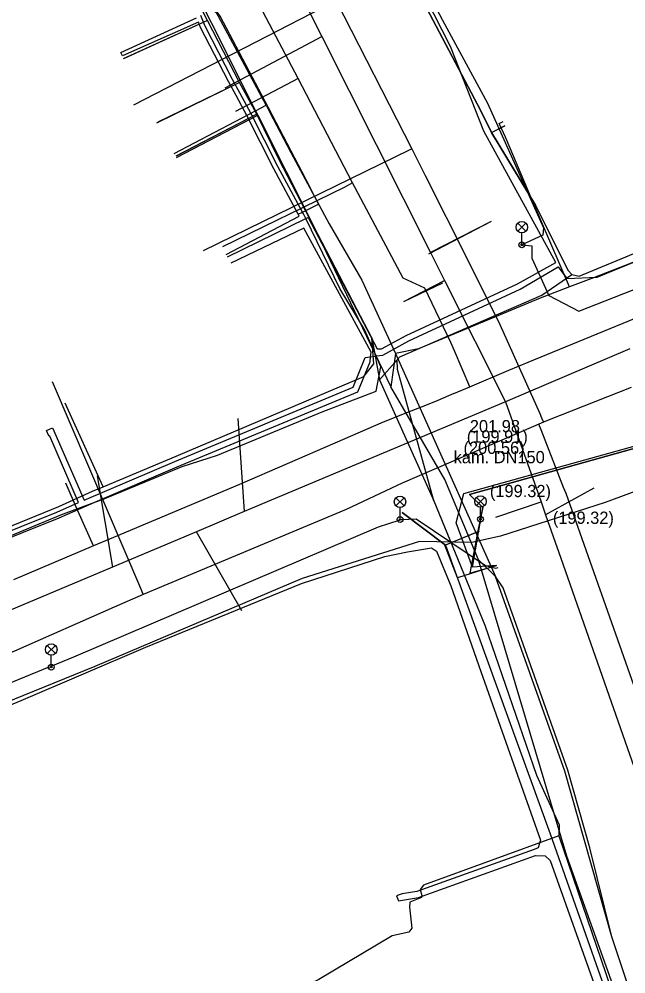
# Model space of a CAD drawing. Extents: x -596228 to -595156, y -1161235 to -1159373.
# Drawn here: x -595920.9 to -595881.3, y -1160772.6 to -1160710.3 of the extents above; entities that cross this region are included whole.
import ezdxf

# ---------------------------------------------------------------- set-up
doc = ezdxf.new("R2010")
doc.units = 0
for name, color, linetype in [('Vrstva 1', 7, 'Continuous'), ('Vrstva 12', 7, 'Continuous'), ('Vrstva 14', 7, 'Continuous'), ('Vrstva 19', 7, 'Continuous'), ('Vrstva 33', 7, 'Continuous'), ('Vrstva 42', 7, 'Continuous'), ('Vrstva 55', 7, 'Continuous'), ('Vrstva 58', 7, 'Continuous'), ('Vrstva 9', 7, 'Continuous')]:
    doc.layers.add(name, color=color, linetype=linetype)

msp = doc.modelspace()

# ---------------------------------------------------------------- linework, layer by layer
at = {"layer": 'Vrstva 1'}
for p, q in [((-595890.14, -1160723.5), (-595894.225, -1160725.63)), ((-595890.14, -1160723.5), (-595894.096, -1160725.519)), ((-595895.84, -1160728.73), (-595893.175, -1160727.35)), ((-595895.84, -1160728.73), (-595893.291, -1160727.511)), ((-595883.44, -1160740.9), (-595886.577, -1160742.651)), ((-595883.44, -1160740.9), (-595886.577, -1160742.651)), ((-595889.83, -1160742.8), (-595886.879, -1160741.799)), ((-595889.83, -1160742.8), (-595886.878, -1160741.799))]:
    msp.add_line(p, q, dxfattribs=at)
at = {"layer": 'Vrstva 12'}
for p, q in [((-595908.65, -1160710.37), (-595914.09, -1160712.85)), ((-595906.56, -1160714.41), (-595908.65, -1160710.37)), ((-595906.56, -1160714.41), (-595911.88, -1160717.02)), ((-595905.42, -1160716.48), (-595906.56, -1160714.41)), ((-595904.82, -1160715.91), (-595905.1, -1160715.38)), ((-595910.81, -1160719.06), (-595905.51, -1160716.27)), ((-595905.42, -1160716.48), (-595910.71, -1160719.23)), ((-595905.51, -1160716.27), (-595904.82, -1160715.91)), ((-595905.51, -1160716.27), (-595905.37, -1160716.55)), ((-595910.66, -1160719.32), (-595905.37, -1160716.55)), ((-595890.12, -1160717.68), (-595889.24, -1160717.24)), ((-595890.06, -1160717.78), (-595890.12, -1160717.68)), ((-595889.31, -1160719), (-595890.06, -1160717.78)), ((-595887.23, -1160722.44), (-595889.31, -1160719)), ((-595880.5, -1160726.03), (-595883.46, -1160727.17)), ((-595883.46, -1160727.17), (-595885.02, -1160727.77)), ((-595897.91, -1160731.09), (-595898.53, -1160729.93)), ((-595897.91, -1160731.09), (-595897.68, -1160732.4)), ((-595897.68, -1160732.4), (-595897.43, -1160733.84)), ((-595896.37, -1160732.11), (-595896.69, -1160734.3)), ((-595896.37, -1160732.11), (-595889.84, -1160746.67)), ((-595915.46, -1160740.82), (-595917.94, -1160735.35)), ((-595890.97, -1160745.58), (-595889.84, -1160746.67)), ((-595877.12, -1160785.47), (-595882.26, -1160770.2))]:
    msp.add_line(p, q, dxfattribs=at)
for points in [[(-595920.87, -1160686.25), (-595919.36, -1160689.21), (-595911.28, -1160704.76), (-595905.51, -1160716.27)], [(-595890.12, -1160717.68), (-595890.8, -1160716.28), (-595892.68, -1160712.73), (-595895.37, -1160707.59), (-595897.16, -1160704.21), (-595899.45, -1160699.85)], [(-595905.1, -1160715.38), (-595908.88, -1160708.31), (-595910.3, -1160705.67), (-595912.55, -1160701.31)], [(-595908.65, -1160710.37), (-595909.66, -1160708.38), (-595911.55, -1160704.72), (-595911.94, -1160704.01)], [(-595898.53, -1160729.93), (-595898.91, -1160729.22), (-595903.96, -1160719.46), (-595905.42, -1160716.48)], [(-595904.82, -1160715.91), (-595904.6, -1160716.33), (-595903.21, -1160718.99), (-595900.71, -1160723.64), (-595898.57, -1160727.32), (-595896.37, -1160732.11)], [(-595905.37, -1160716.55), (-595901.69, -1160723.87), (-595896.69, -1160734.3)], [(-595885.02, -1160727.77), (-595887.45, -1160722.1), (-595889.19, -1160718), (-595889.61, -1160717.09), (-595889.36, -1160716.97)], [(-595884.86, -1160726.96), (-595885.1, -1160726.69), (-595887.23, -1160722.44)], [(-595884.86, -1160726.96), (-595884.4, -1160727.07), (-595881.23, -1160725.75)], [(-595897.43, -1160733.84), (-595896.26, -1160732.53), (-595896.1, -1160732.34), (-595886.83, -1160728.31), (-595884.86, -1160726.96)], [(-595885.02, -1160727.77), (-595886.93, -1160728.51), (-595894.87, -1160731.8), (-595896.37, -1160732.11)], [(-595915.46, -1160740.82), (-595910.68, -1160738.82), (-595898.45, -1160733.62), (-595897.79, -1160732.79), (-595897.91, -1160731.09)], [(-595897.43, -1160733.84), (-595893.88, -1160741.74), (-595890.54, -1160749.86), (-595887.17, -1160759.65), (-595885.69, -1160762.88), (-595885.71, -1160763.61)], [(-595890.97, -1160745.58), (-595893.16, -1160740.35), (-595896.69, -1160734.3)], [(-595926.38, -1160745.37), (-595923.37, -1160744.15), (-595918.35, -1160742.11), (-595916.16, -1160741.11), (-595915.46, -1160740.82)], [(-595877.8, -1160785.64), (-595885.2, -1160764.94), (-595890.97, -1160745.58)], [(-595882.26, -1160770.2), (-595883.69, -1160764.4), (-595885.14, -1160759.33), (-595889.36, -1160747.42), (-595889.84, -1160746.67)], [(-595882.26, -1160770.2), (-595885.33, -1160759.39), (-595889.84, -1160746.67)], [(-595885.71, -1160763.61), (-595894.54, -1160766.83), (-595894.76, -1160767.11), (-595894.66, -1160767.51), (-595894.68, -1160767.63), (-595895.43, -1160767.93), (-595895.47, -1160768.26), (-595895.31, -1160769.63), (-595895.51, -1160769.89), (-595896.59, -1160770.14), (-595901.37, -1160772.99), (-595906.61, -1160775.68), (-595911.39, -1160776.34), (-595914.12, -1160776.08), (-595915.86, -1160775.08), (-595916.37, -1160774.12)], [(-595885.71, -1160763.61), (-595881.71, -1160775.34), (-595877.36, -1160787.44)]]:
    msp.add_lwpolyline(points, dxfattribs=at)
at = {"layer": 'Vrstva 14'}
for p, q in [((-595881.004, -1160734.33), (-595886.451, -1160736.489)), ((-595886.963, -1160736.031), (-595886.851, -1160736.305)), ((-595886.851, -1160736.305), (-595886.721, -1160736.607)), ((-595887.37, -1160736.884), (-595895.93, -1160740.59)), ((-595887.012, -1160736.732), (-595887.37, -1160736.884)), ((-595886.721, -1160736.607), (-595887.012, -1160736.732)), ((-595886.87, -1160737.09), (-595887.012, -1160736.732)), ((-595886.451, -1160736.489), (-595886.721, -1160736.607))]:
    msp.add_line(p, q, dxfattribs=at)
for points in [[(-595926.572, -1160658.791), (-595922.331, -1160666.975), (-595922.126, -1160667.364), (-595921.558, -1160668.432), (-595918.38, -1160674.459), (-595917.977, -1160675.231), (-595917.527, -1160676.095), (-595915.091, -1160680.758), (-595912.991, -1160684.79), (-595910.854, -1160688.921), (-595910.362, -1160689.864), (-595909.965, -1160690.625), (-595908.347, -1160693.726), (-595907.059, -1160696.132), (-595906.224, -1160697.692), (-595904.062, -1160701.813), (-595903.372, -1160703.143), (-595900.25, -1160709.091), (-595895.314, -1160718.754), (-595894.439, -1160720.494), (-595891.712, -1160725.893), (-595889.572, -1160730.225), (-595886.963, -1160736.031)], [(-595900.25, -1160709.091), (-595900.414, -1160709.18), (-595913.485, -1160715.898)], [(-595895.314, -1160718.754), (-595895.476, -1160718.834), (-595908.926, -1160725.411)], [(-595912.84, -1160747.84), (-595912.94, -1160747.61), (-595918.761, -1160733.954)], [(-595867.479, -1160791.46), (-595868.128, -1160789.63), (-595871.59, -1160779.9), (-595885.24, -1160741.26), (-595885.404, -1160740.857), (-595886.87, -1160737.09)], [(-595895.93, -1160740.59), (-595899.6, -1160742.31), (-595912.84, -1160747.84), (-595914.74, -1160748.68), (-595921.25, -1160751.56), (-595923.91, -1160752.66), (-595927.19, -1160754.01), (-595932.66, -1160756.26), (-595933.82, -1160756.75), (-595937.68, -1160758.4), (-595942.37, -1160760.37), (-595945.06, -1160761.51), (-595946.46, -1160762.1), (-595947.85, -1160762.68), (-595962.12, -1160768.63), (-595963.29, -1160769.12), (-595970.02, -1160772), (-595976.93, -1160774.96), (-595977.43, -1160775.17), (-595987.69, -1160779.56), (-595997.69, -1160783.61)]]:
    msp.add_lwpolyline(points, dxfattribs=at)
at = {"layer": 'Vrstva 19'}
for p, q in [((-595902.73, -1160714.155), (-595906.817, -1160716.311)), ((-595899.724, -1160721.268), (-595907.67, -1160725.14)), ((-595899.183, -1160720.963), (-595899.724, -1160721.268)), ((-595891.52, -1160734.29), (-595892.52, -1160731.93))]:
    msp.add_line(p, q, dxfattribs=at)
for points in [[(-595892.52, -1160731.93), (-595892.76, -1160731.39), (-595894.452, -1160727.858), (-595895.878, -1160727.201), (-595899.183, -1160720.963), (-595902.73, -1160714.155), (-595906.047, -1160707.823), (-595906.981, -1160706.086), (-595909.275, -1160701.719), (-595909.609, -1160700.941), (-595911.016, -1160698.292), (-595913.475, -1160693.663), (-595913.599, -1160693.324), (-595913.952, -1160692.775), (-595915.467, -1160689.84), (-595917.901, -1160685.194), (-595920.56, -1160680.118), (-595920.628, -1160679.824), (-595922.636, -1160675.96), (-595924.387, -1160672.545), (-595925.964, -1160669.55), (-595928.051, -1160665.682), (-595931.02, -1160659.823)], [(-595892.57, -1160734.72), (-595891.52, -1160734.29), (-595888.97, -1160733.21), (-595887.72, -1160732.68), (-595879.93, -1160729.49), (-595877.77, -1160728.55), (-595877.08, -1160728.26), (-595875.68, -1160727.65), (-595875.53, -1160727.58)], [(-595892.57, -1160734.72), (-595893.61, -1160735.18), (-595894.41, -1160735.51), (-595895.48, -1160735.93), (-595897.19, -1160736.6), (-595900.34, -1160737.98), (-595906.56, -1160740.67), (-595914.77, -1160744.12), (-595916.09, -1160744.68), (-595921.31, -1160746.9)], [(-595916.09, -1160744.68), (-595917.1, -1160742.39), (-595917.9, -1160740.57)]]:
    msp.add_lwpolyline(points, dxfattribs=at)
at = {"layer": 'Vrstva 33'}
for p, q in [((-595888.395, -1160723.605), (-595887.865, -1160724.135)), ((-595888.395, -1160724.135), (-595887.865, -1160723.605)), ((-595888.13, -1160725.02), (-595888.13, -1160724.245)), ((-595896.345, -1160741.535), (-595895.815, -1160742.065)), ((-595896.345, -1160742.065), (-595895.815, -1160741.535)), ((-595891.095, -1160741.515), (-595890.565, -1160742.045)), ((-595891.095, -1160742.045), (-595890.565, -1160741.515)), ((-595896.08, -1160742.95), (-595896.08, -1160742.175)), ((-595890.83, -1160742.93), (-595890.83, -1160742.155)), ((-595919.105, -1160751.175), (-595918.575, -1160751.705)), ((-595919.105, -1160751.705), (-595918.575, -1160751.175)), ((-595918.84, -1160752.59), (-595918.84, -1160751.815))]:
    msp.add_line(p, q, dxfattribs=at)
for centre, radius in [((-595888.13, -1160723.87), 0.375), ((-595888.13, -1160725.02), 0.19), ((-595888.13, -1160725.02), 0.05), ((-595896.08, -1160741.8), 0.375), ((-595890.83, -1160741.78), 0.375), ((-595896.08, -1160742.95), 0.19), ((-595896.08, -1160742.95), 0.05), ((-595890.83, -1160742.93), 0.19), ((-595890.83, -1160742.93), 0.05), ((-595918.84, -1160751.44), 0.375), ((-595918.84, -1160752.59), 0.19), ((-595918.84, -1160752.59), 0.05)]:
    msp.add_circle(centre, radius, dxfattribs=at)
at = {"layer": 'Vrstva 42'}
for points in [[(-595901.404, -1160722.363), (-595901.974, -1160721.234), (-595904.657, -1160716.079), (-595907.825, -1160710.079), (-595907.999, -1160709.855), (-595908.124, -1160709.858), (-595908.203, -1160709.44), (-595908.234, -1160709.273), (-595909.02, -1160707.897), (-595911.61, -1160702.881), (-595913.56, -1160699.059), (-595915.722, -1160694.823), (-595916.748, -1160693.17)], [(-595907.33, -1160725.799), (-595902.238, -1160723.302), (-595902.082, -1160723.225), (-595897.58, -1160731.82), (-595897.29, -1160731.801), (-595895.681, -1160730.932), (-595888.423, -1160727.558), (-595885.922, -1160726.168), (-595890.613, -1160717.607), (-595892.778, -1160712.06), (-595900.271, -1160697.381), (-595901.408, -1160695.148), (-595900.242, -1160694.595), (-595899.79, -1160694.892)], [(-595925.354, -1160745.618), (-595918.221, -1160742.653), (-595916.001, -1160741.822), (-595915.506, -1160741.637), (-595910.306, -1160739.503), (-595908, -1160738.755), (-595901.157, -1160735.928), (-595897.633, -1160734.584), (-595897.324, -1160732.991), (-595897.641, -1160732.271), (-595898.397, -1160730.551), (-595900.003, -1160727.871), (-595902.238, -1160723.302), (-595902.389, -1160722.994), (-595902.451, -1160722.878), (-595904.049, -1160719.908), (-595905.799, -1160716.473), (-595906.504, -1160715.136), (-595907.017, -1160714.214), (-595908.819, -1160710.705), (-595909.088, -1160710.055)], [(-595907.425, -1160725.642), (-595902.652, -1160723.138), (-595902.72, -1160723.011), (-595904.315, -1160720.047), (-595906.065, -1160716.611), (-595906.768, -1160715.279), (-595907.282, -1160714.355), (-595909.091, -1160710.831), (-595909.228, -1160710.483), (-595914.184, -1160712.69), (-595914.292, -1160712.459), (-595909.364, -1160710.209)], [(-595902.699, -1160723), (-595902.72, -1160723.011), (-595902.753, -1160723.027), (-595902.72, -1160723.011), (-595902.451, -1160722.878), (-595901.404, -1160722.363)], [(-595934.6, -1160749.584), (-595932.554, -1160748.571), (-595932.27, -1160748.43), (-595931.848, -1160748.25), (-595931.34, -1160748.035), (-595928.323, -1160746.752), (-595925.354, -1160745.618), (-595923.01, -1160744.723), (-595918.328, -1160742.842), (-595916.894, -1160742.204), (-595916.001, -1160741.822), (-595910.627, -1160739.525), (-595898.834, -1160734.62), (-595898.036, -1160732.667), (-595898, -1160732.327), (-595897.967, -1160732.02), (-595902.348, -1160723.934), (-595907.114, -1160726.226)], [(-595923.156, -1160744.351), (-595918.484, -1160742.474), (-595917.054, -1160741.837), (-595918.927, -1160737.504), (-595918.996, -1160737.483), (-595919.145, -1160737.148), (-595918.758, -1160736.976), (-595916.689, -1160741.683), (-595910.782, -1160739.156), (-595899.141, -1160734.315), (-595898.352, -1160732.384), (-595898, -1160732.327), (-595897.725, -1160732.282), (-595897.641, -1160732.271), (-595897.205, -1160732.215), (-595895.501, -1160731.289), (-595888.237, -1160727.913), (-595885.757, -1160726.451), (-595885.205, -1160727.218), (-595883.216, -1160727.137), (-595882.208, -1160726.723), (-595877.9, -1160724.955)], [(-595874.569, -1160738.85), (-595882.702, -1160741.846), (-595889.513, -1160744.047), (-595891.393, -1160744.454), (-595894.802, -1160744.39), (-595902.471, -1160746.816), (-595915.993, -1160752.54), (-595925.914, -1160756.568), (-595931.82, -1160759.113), (-595932.225, -1160759.288), (-595932.613, -1160759.455), (-595932.828, -1160759.547), (-595933.027, -1160759.633), (-595934.282, -1160760.174), (-595934.102, -1160760.967), (-595933.081, -1160764.099)], [(-595929.91, -1160758.548), (-595920.807, -1160754.77), (-595912.661, -1160751.283), (-595902.501, -1160747.122), (-595897.076, -1160745.358), (-595895.585, -1160745.06), (-595894.023, -1160744.801), (-595893.702, -1160745.023), (-595892.764, -1160747.284), (-595890.804, -1160752.868), (-595886.907, -1160763.892), (-595887.055, -1160764.394), (-595887.335, -1160764.499), (-595894.985, -1160767.238), (-595895.938, -1160767.395), (-595896.128, -1160767.458), (-595896.314, -1160767.532), (-595896.19, -1160767.841), (-595894.885, -1160767.626), (-595887.235, -1160764.889), (-595886.612, -1160764.902), (-595886.287, -1160765.226), (-595883.314, -1160773.524)]]:
    msp.add_lwpolyline(points, dxfattribs=at)
at = {"layer": 'Vrstva 55'}
for points in [[(-595889.79, -1160745.95), (-595891.36, -1160746.06), (-595892.42, -1160743.16), (-595891.92, -1160741.26), (-595875.35, -1160736.65), (-595872.33, -1160733.76), (-595875.48, -1160725.74), (-595875.785, -1160723.596), (-595873.304, -1160722.355), (-595839.562, -1160708.213), (-595811.03, -1160696.553), (-595790.3, -1160687.72), (-595790.51, -1160686.78), (-595788.97, -1160684.34)], [(-595898.22, -1160701.02), (-595893.31, -1160710.35), (-595890.38, -1160715.78), (-595886.71, -1160723.9), (-595886.77, -1160724.39), (-595888.13, -1160725.02)], [(-595889.79, -1160745.95), (-595891.36, -1160746.06), (-595890.68, -1160742.18), (-595891.55, -1160741.32), (-595875.14, -1160736.73), (-595863.03, -1160734.65), (-595842.305, -1160724.861), (-595836.396, -1160723.626), (-595810.202, -1160712.161), (-595794.144, -1160748.847), (-595820.885, -1160760.263), (-595826.343, -1160763.884), (-595835.327, -1160767.526), (-595847.836, -1160771.52)], [(-595888.13, -1160725.02), (-595887.47, -1160725.094), (-595887.47, -1160725.89), (-595886.36, -1160728.33), (-595884.41, -1160729.36), (-595875.71, -1160725.93), (-595872.39, -1160733.93), (-595875.14, -1160736.73), (-595891.55, -1160741.32), (-595890.68, -1160742.18), (-595890.97, -1160743.47), (-595891.52, -1160746.45), (-595889.79, -1160745.95)], [(-595889.79, -1160745.95), (-595892.34, -1160746.77), (-595893.15, -1160744.63), (-595890.92, -1160743.72), (-595893.11, -1160744.63), (-595895.93, -1160742.49), (-595893.11, -1160744.63), (-595886.28, -1160763.47), (-595880.73, -1160779.23), (-595878.5, -1160778.95), (-595880.73, -1160779.23), (-595875.72, -1160792.93), (-595872.94, -1160800.17), (-595869.94, -1160799.07), (-595859.83, -1160795.8), (-595860.65, -1160793.25), (-595859.74, -1160793.06)], [(-595970.72, -1160774.17), (-595963.24, -1160771.03), (-595962.45, -1160770.68), (-595946.91, -1160764.24), (-595946.81, -1160764.21), (-595940.98, -1160761.6), (-595935.62, -1160759.4), (-595918.979, -1160752.583), (-595918.84, -1160752.59), (-595918.84, -1160752.526), (-595917.36, -1160751.92), (-595897.49, -1160743.44), (-595896.144, -1160743), (-595896.08, -1160742.95), (-595895.99, -1160742.95), (-595895.02, -1160742.92), (-595890.5, -1160745.95), (-595889.82, -1160746.14), (-595889.665, -1160746.088)]]:
    msp.add_lwpolyline(points, dxfattribs=at)
at = {"layer": 'Vrstva 58'}
for p, q in [((-595908.65, -1160710.37), (-595914.15, -1160712.87)), ((-595906.56, -1160714.41), (-595908.65, -1160710.37)), ((-595906.56, -1160714.41), (-595911.97, -1160717.07)), ((-595905.42, -1160716.48), (-595906.56, -1160714.41)), ((-595905.42, -1160716.48), (-595910.65, -1160719.2)), ((-595890.12, -1160717.68), (-595889.21, -1160717.22)), ((-595915.46, -1160740.82), (-595917.93, -1160735.36))]:
    msp.add_line(p, q, dxfattribs=at)
for points in [[(-595903.92, -1160691.06), (-595902.29, -1160694.19), (-595901.08, -1160696.57), (-595899.45, -1160699.85), (-595897.16, -1160704.21), (-595895.37, -1160707.59), (-595892.68, -1160712.73), (-595890.8, -1160716.28), (-595890.12, -1160717.68), (-595887.23, -1160722.44), (-595885.1, -1160726.69), (-595884.86, -1160726.96), (-595884.4, -1160727.07), (-595867.86, -1160720.21)], [(-595890.12, -1160717.68), (-595890.8, -1160716.28), (-595892.68, -1160712.73), (-595895.37, -1160707.59), (-595897.16, -1160704.21), (-595899.45, -1160699.85)], [(-595908.65, -1160710.37), (-595909.66, -1160708.38), (-595911.55, -1160704.72), (-595912.09, -1160703.76)], [(-595897.91, -1160731.09), (-595898.91, -1160729.22), (-595903.96, -1160719.46), (-595905.42, -1160716.48)], [(-595884.86, -1160726.96), (-595885.1, -1160726.69), (-595887.23, -1160722.44), (-595890.12, -1160717.68)], [(-595884.86, -1160726.96), (-595884.4, -1160727.07), (-595867.86, -1160720.21), (-595865.04, -1160719.06)], [(-595893.88, -1160741.74), (-595896.25, -1160733.15), (-595896.26, -1160732.53), (-595896.1, -1160732.34), (-595886.83, -1160728.31), (-595884.86, -1160726.96)], [(-595915.46, -1160740.82), (-595910.68, -1160738.82), (-595898.45, -1160733.62), (-595897.79, -1160732.79), (-595897.91, -1160731.09)], [(-595897.91, -1160731.09), (-595897.43, -1160733.84), (-595893.88, -1160741.74)], [(-595926.38, -1160745.37), (-595923.37, -1160744.15), (-595918.35, -1160742.11), (-595916.16, -1160741.11), (-595915.46, -1160740.82)], [(-595893.88, -1160741.74), (-595890.54, -1160749.86), (-595887.17, -1160759.65), (-595885.69, -1160762.88), (-595885.71, -1160763.61)], [(-595885.71, -1160763.61), (-595894.54, -1160766.83), (-595894.76, -1160767.11), (-595894.66, -1160767.51), (-595894.68, -1160767.63), (-595895.43, -1160767.93), (-595895.47, -1160768.26), (-595895.31, -1160769.63), (-595895.51, -1160769.89), (-595896.59, -1160770.14), (-595901.37, -1160772.99), (-595906.61, -1160775.68), (-595911.39, -1160776.34), (-595914.12, -1160776.08), (-595915.86, -1160775.08), (-595916.37, -1160774.13)]]:
    msp.add_lwpolyline(points, dxfattribs=at)
at = {"layer": 'Vrstva 9'}
for p, q in [((-595907.489, -1160714.76), (-595901.192, -1160711.424)), ((-595881.08, -1160731.81), (-595889.188, -1160735.27)), ((-595906.655, -1160736.364), (-595906.245, -1160742.44)), ((-595915.84, -1160740.1), (-595914.85, -1160746.058)), ((-595906.41, -1160748.92), (-595909.361, -1160743.75)), ((-595885.58, -1160745.47), (-595879.66, -1160762.44))]:
    msp.add_line(p, q, dxfattribs=at)
for points in [[(-595907.171, -1160699.546), (-595906.722, -1160700.438), (-595906.046, -1160701.782), (-595901.192, -1160711.424), (-595894.096, -1160725.519), (-595893.175, -1160727.35), (-595889.188, -1160735.27)], [(-595889.188, -1160735.27), (-595906.245, -1160742.44), (-595909.361, -1160743.75), (-595914.85, -1160746.058), (-595924.115, -1160749.953), (-595928.103, -1160751.629)], [(-595889.188, -1160735.27), (-595886.879, -1160741.799), (-595886.577, -1160742.651), (-595885.58, -1160745.47)]]:
    msp.add_lwpolyline(points, dxfattribs=at)

# ---------------------------------------------------------------- texts
at = {"layer": 'Vrstva 12'}
for s, p in [('201.98', (-595891.527, -1160737.26)), ('(199.91)', (-595891.723, -1160737.928)), ('(200.56)', (-595891.937, -1160738.67)), ('kam. DN150', (-595892.58, -1160739.28)), ('(199.32)', (-595890.215, -1160741.494)), ('(199.32)', (-595886.109, -1160743.238))]:
    msp.add_text(s, height=0.8, dxfattribs=at).set_placement(p)

doc.saveas('drawing.dxf')
